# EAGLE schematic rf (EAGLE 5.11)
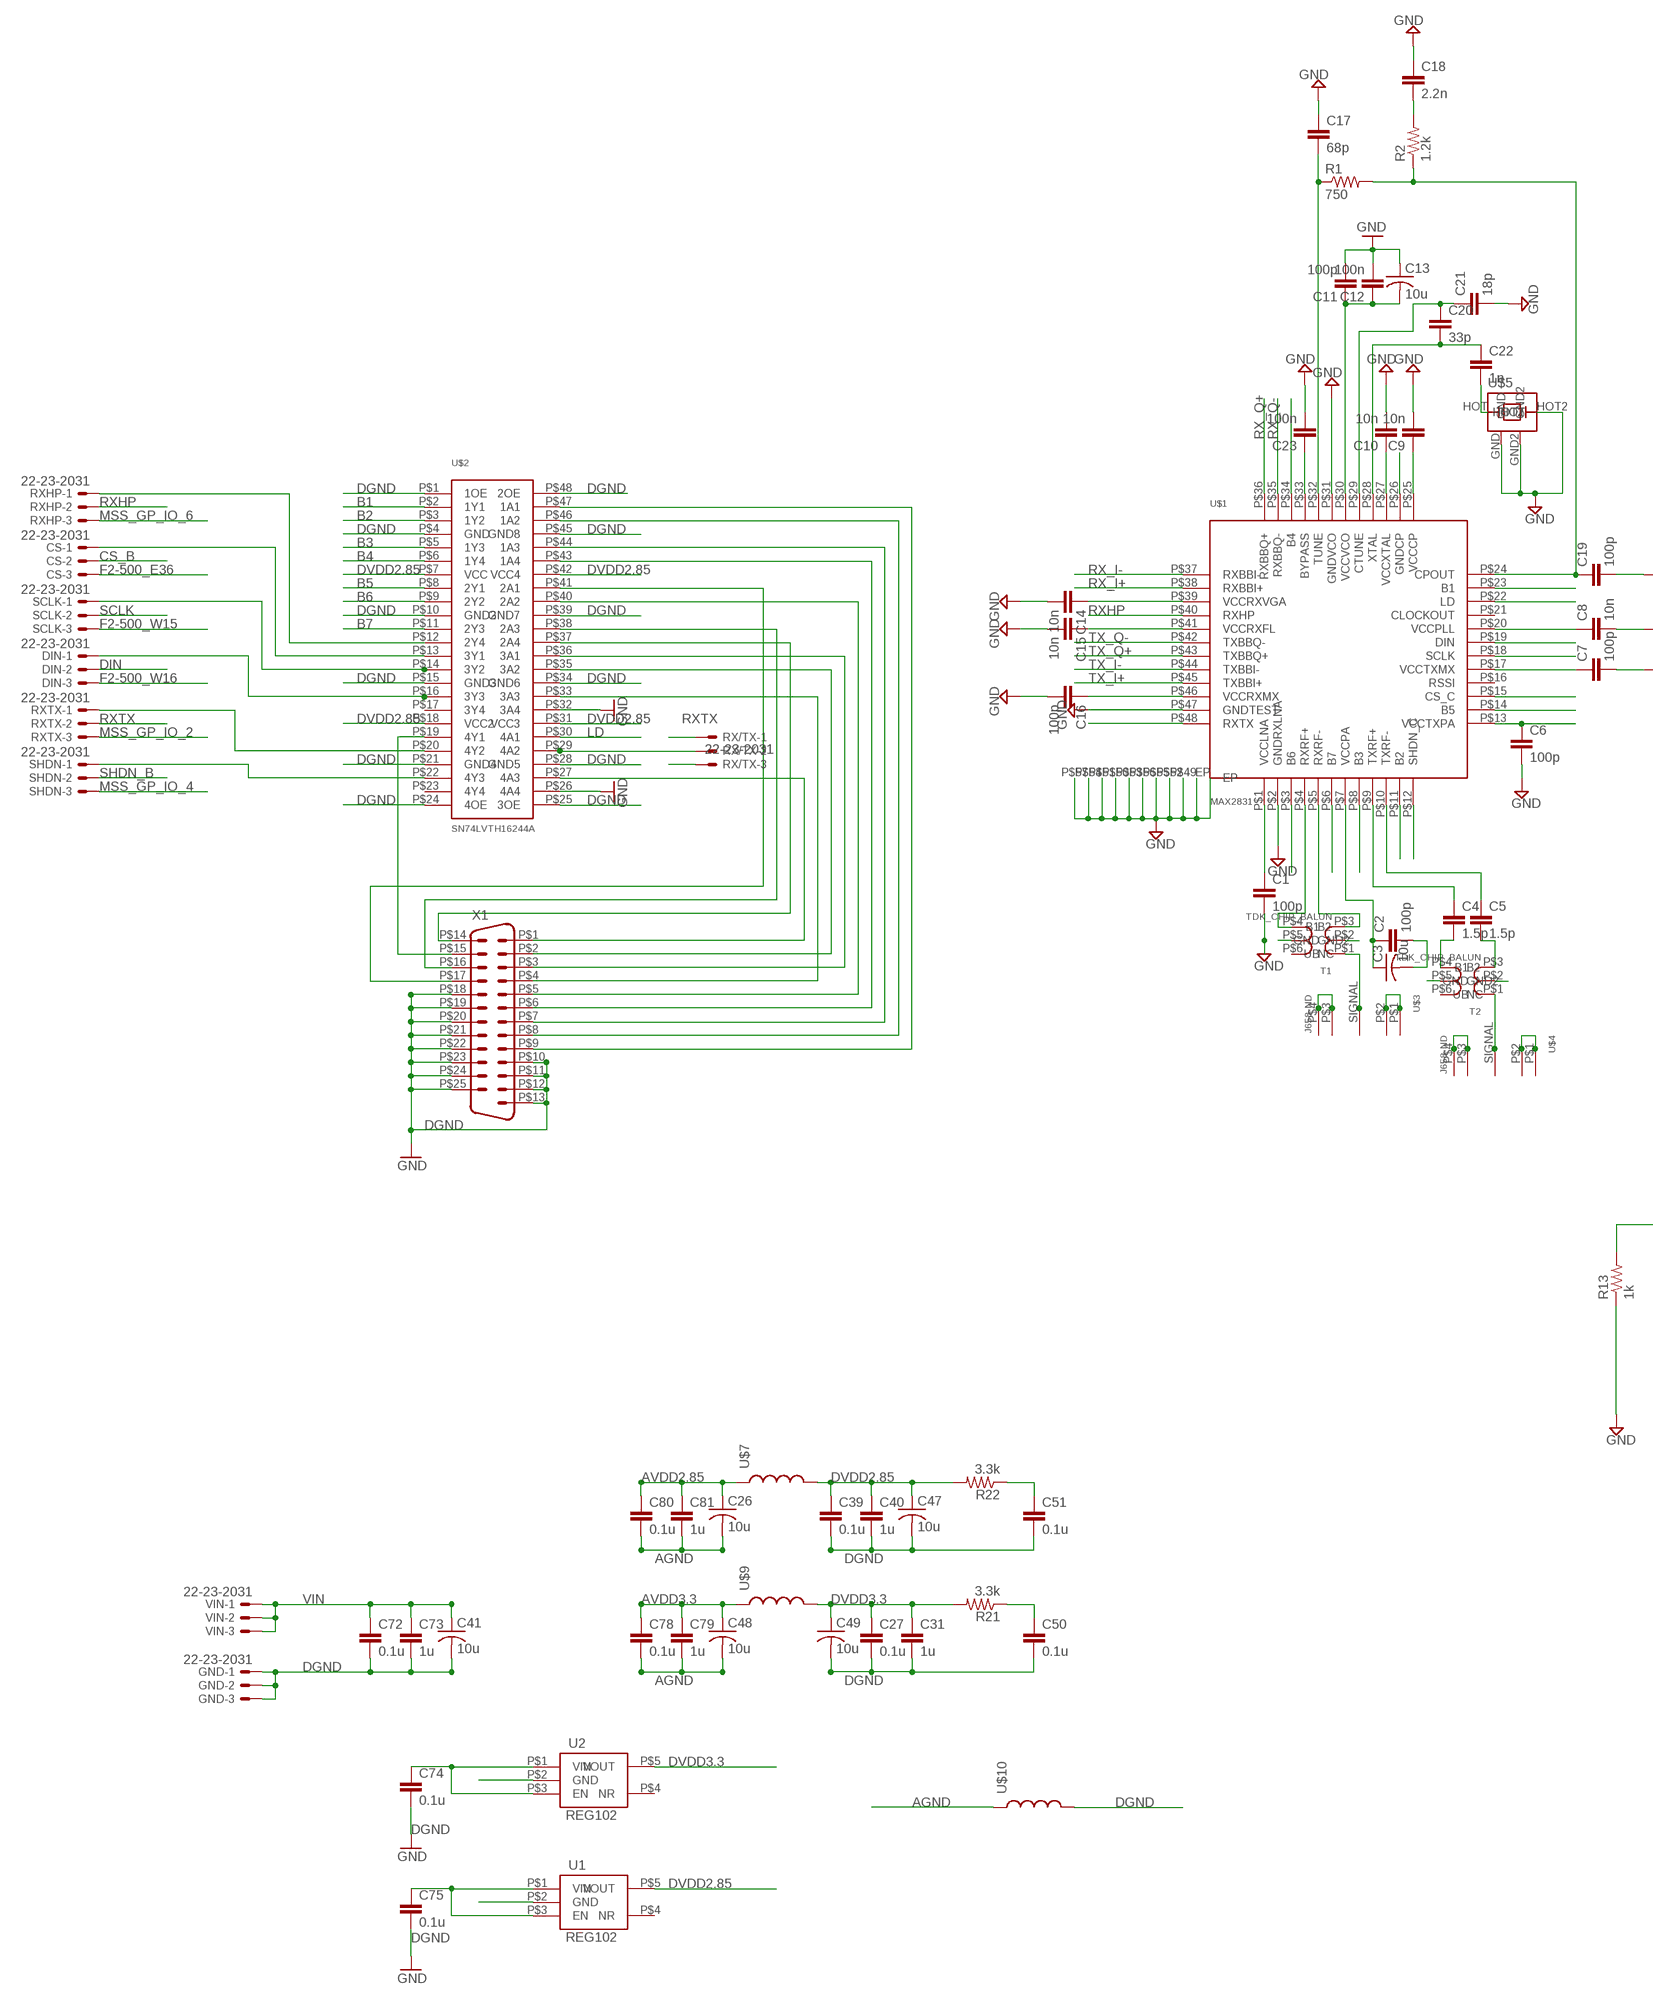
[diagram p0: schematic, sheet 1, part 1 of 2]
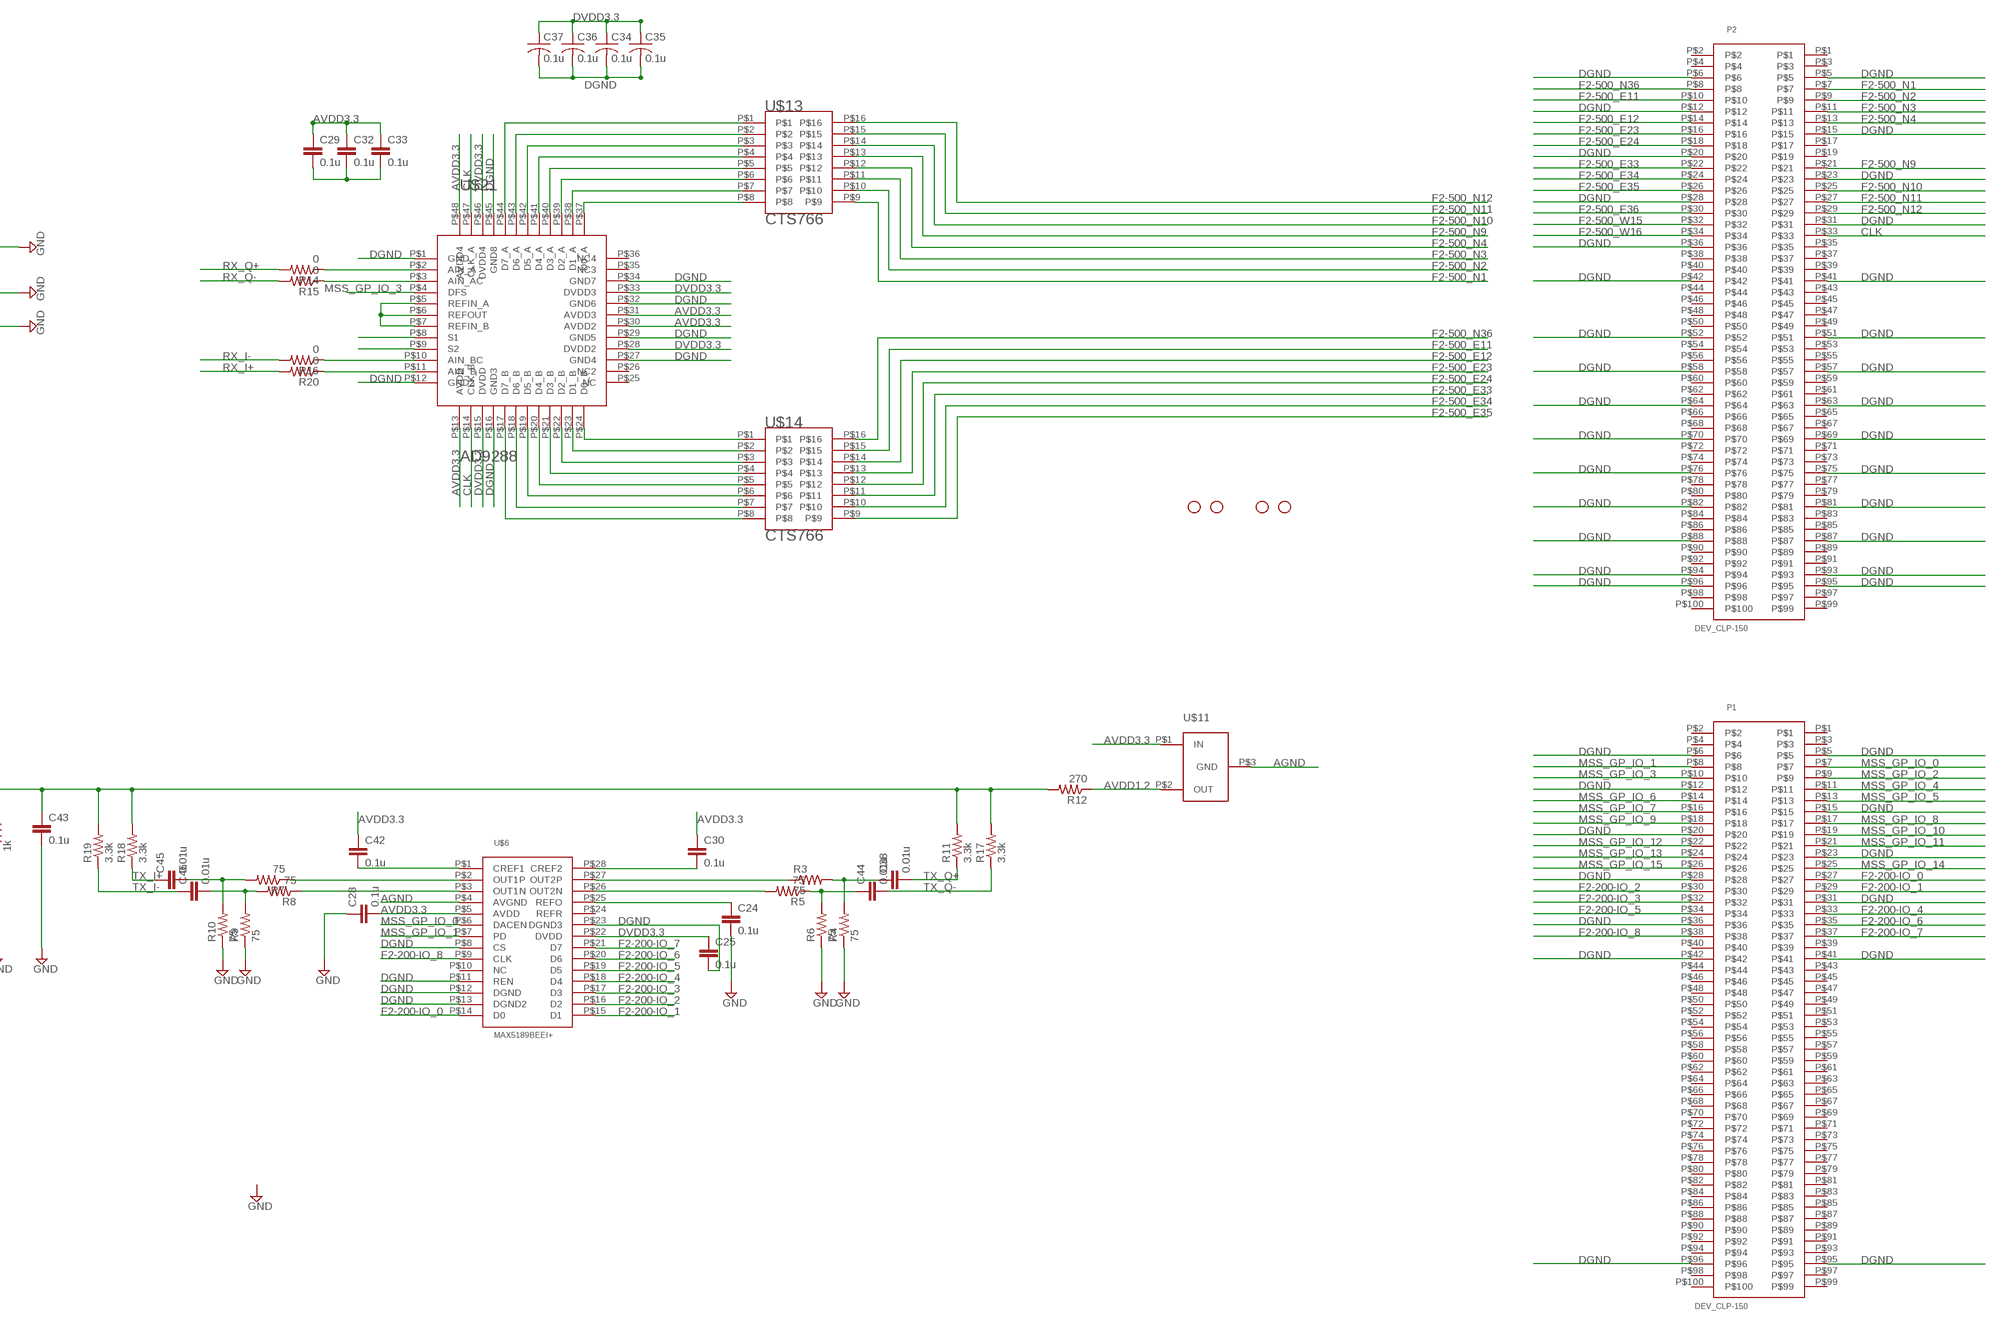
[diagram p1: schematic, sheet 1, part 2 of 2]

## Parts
C1  100p  CAP0402-CAP  [0402-CAP]
C2  100p  CAP0402-CAP  [0402-CAP]
C3  10u  C-USC0805  [C0805]
C4  1.5p  CAP0402-CAP  [0402-CAP]
C5  1.5p  CAP0402-CAP  [0402-CAP]
C6  100p  CAP0402-CAP  [0402-CAP]
C7  100p  CAP0402-CAP  [0402-CAP]
C8  10n  CAP0402-CAP  [0402-CAP]
C9  10n  CAP0402-CAP  [0402-CAP]
C10  10n  CAP0402-CAP  [0402-CAP]
C11  100p  CAP0402-CAP  [0402-CAP]
C12  100n  CAP0402-CAP  [0402-CAP]
C13  10u  C-USC0805  [C0805]
C14  10n  CAP0402-CAP  [0402-CAP]
C15  10n  CAP0402-CAP  [0402-CAP]
C16  100p  CAP0402-CAP  [0402-CAP]
C17  68p  CAP0402-CAP  [0402-CAP]
C18  2.2n  CAP0402-CAP  [0402-CAP]
C19  100p  CAP0402-CAP  [0402-CAP]
C20  33p  CAP0402-CAP  [0402-CAP]
C21  18p  CAP0402-CAP  [0402-CAP]
C22  1n  CAP0402-CAP  [0402-CAP]
C23  100n  CAP0402-CAP  [0402-CAP]
C24  0.1u  CAP0603-CAP  [0603-CAP]
C25  0.1u  CAP0603-CAP  [0603-CAP]
C26  10u  C-USC0805  [C0805]
C27  0.1u  CAP0603-CAP  [0603-CAP]
C28  0.1u  CAP0603-CAP  [0603-CAP]
C29  0.1u  CAP0603-CAP  [0603-CAP]
C30  0.1u  CAP0603-CAP  [0603-CAP]
C31  1u  CAP0603-CAP  [0603-CAP]
C32  0.1u  CAP0603-CAP  [0603-CAP]
C33  0.1u  CAP0603-CAP  [0603-CAP]
C34  0.1u  C-USC0603  [C0603]
C35  0.1u  C-USC0603  [C0603]
C36  0.1u  C-USC0603  [C0603]
C37  0.1u  C-USC0603  [C0603]
C38  0.01u  CAP0603-CAP  [0603-CAP]
C39  0.1u  CAP0603-CAP  [0603-CAP]
C40  1u  CAP0603-CAP  [0603-CAP]
C41  10u  C-USC0805  [C0805]
C42  0.1u  CAP0603-CAP  [0603-CAP]
C43  0.1u  CAP0603-CAP  [0603-CAP]
C44  0.01u  CAP0603-CAP  [0603-CAP]
C45  0.01u  CAP0603-CAP  [0603-CAP]
C46  0.01u  CAP0603-CAP  [0603-CAP]
C47  10u  C-USC0805  [C0805]
C48  10u  C-USC0805  [C0805]
C49  10u  C-USC0805  [C0805]
C50  0.1u  CAP0603-CAP  [0603-CAP]
C51  0.1u  CAP0603-CAP  [0603-CAP]
C72  0.1u  CAP0603-CAP  [0603-CAP]
C73  1u  CAP0603-CAP  [0603-CAP]
C74  0.1u  CAP0603-CAP  [0603-CAP]
C75  0.1u  CAP0603-CAP  [0603-CAP]
C78  0.1u  CAP0603-CAP  [0603-CAP]
C79  1u  CAP0603-CAP  [0603-CAP]
C80  0.1u  CAP0603-CAP  [0603-CAP]
C81  1u  CAP0603-CAP  [0603-CAP]
CS  22-23-2031  [22-23-2031]
DIN  22-23-2031  [22-23-2031]
GND  22-23-2031  [22-23-2031]
JP4  STAND-OFF  [STAND-OFF]
JP5  STAND-OFF  [STAND-OFF]
JP6  STAND-OFF  [STAND-OFF]
JP7  STAND-OFF  [STAND-OFF]
P1  DEV_CLP-150  [CLP-150]
P2  DEV_CLP-150  [CLP-150]
R1  750  RESISTOR0402-RES  [0402-RES]
R2  1.2k  RESISTOR0402-RES  [0402-RES]
R3  75  RESISTOR0603-RES  [0603-RES]
R4  75  RESISTOR0603-RES  [0603-RES]
R5  75  RESISTOR0603-RES  [0603-RES]
R6  75  RESISTOR0603-RES  [0603-RES]
R7  75  RESISTOR0603-RES  [0603-RES]
R8  75  RESISTOR0603-RES  [0603-RES]
R9  75  RESISTOR0603-RES  [0603-RES]
R10  75  RESISTOR0603-RES  [0603-RES]
R11  3.3k  RESISTOR0603-RES  [0603-RES]
R12  270  RESISTOR0603-RES  [0603-RES]
R13  1k  RESISTOR0603-RES  [0603-RES]
R14  0  RESISTOR0603-RES  [0603-RES]
R15  0  RESISTOR0603-RES  [0603-RES]
R16  0  RESISTOR0603-RES  [0603-RES]
R17  3.3k  RESISTOR0603-RES  [0603-RES]
R18  3.3k  RESISTOR0603-RES  [0603-RES]
R19  3.3k  RESISTOR0603-RES  [0603-RES]
R20  0  RESISTOR0603-RES  [0603-RES]
R21  3.3k  RESISTOR0603-RES  [0603-RES]
R22  3.3k  RESISTOR0603-RES  [0603-RES]
RX/TX  22-23-2031  [22-23-2031]
RXHP  22-23-2031  [22-23-2031]
RXTX  22-23-2031  [22-23-2031]
SCLK  22-23-2031  [22-23-2031]
SHDN  22-23-2031  [22-23-2031]
T1  TDK_CHIP_BALUN  [BALUN]
T2  TDK_CHIP_BALUN  [BALUN]
U1  REG102  [SOT-5]
U2  REG102  [SOT-5]
U$1  MAX2831  [TQFN-48]
U$2  SN74LVTH16244A  [TSSOP-48]
U$3  J658-ND  [SMA-SMD]
U$4  J658-ND  [SMA-SMD]
U$5  CX3225SB  [CX3225SB]
U$6  MAX5189BEEI+  [QSOP]
U$7  INDUCTOR0603  [0603]
U$9  INDUCTOR0603  [0603]
U$10  INDUCTOR0603  [0603]
U$11  MAX6601  [SOT-3]
U$13  CTS766  [SOIC-16]
U$14  CTS766  [SOIC-16]
U$21  AD9288  [LQFP(ST-48)]
VIN  22-23-2031  [22-23-2031]
X1  DB25  [DB25]

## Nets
AGND: C1.2 C2.2 C3.2 C6.2 C7.2 C8.2 C9.2 C10.2 C11.2 C12.2 C13.1 C14.2 C15.2 C16.2 C17.1 C18.1 C19.2 C21.2 C23.2 C24.2 C26.2 C28.1 C43.2 C48.2 C78.2 C79.2 C80.2 C81.2 R4.1 R6.1 R9.1 R10.1 R13.1 T1.P$2(GND) T1.P$5(GND2) T2.P$2(GND) T2.P$5(GND2) U$1.EP U$1.P$2(GNDRXLNA) U$1.P$26(GNDCP) U$1.P$31(GNDVCO) U$1.P$47(GNDTEST) U$1.P$49(EP_GND1) U$1.P$50(EP_GND2) U$1.P$51(EP_GND3) U$1.P$52(EP_GND4) U$1.P$53(EP_GND5) U$1.P$54(EP_GND6) U$1.P$55(EP_GND7) U$1.P$56(EP_GND8) U$1.P$57(EP_GND9) U$3.P$1(GND1) U$3.P$2(GND2) U$3.P$3(GND3) U$3.P$4(GND4) U$4.P$1(GND1) U$4.P$2(GND2) U$4.P$3(GND3) U$4.P$4(GND4) U$5.GND U$5.GND2 U$5.HOT2 U$6.P$4(AVGND) U$10.1 U$11.P$3(GND) ; supply symbol labelled GND
AVDD1.2: R12.1 U$11.P$2(OUT)
AVDD2.85: C1.1 C7.1 C8.1 C9.1 C10.1 C11.1 C12.1 C13.2 C14.1 C15.1 C16.1 C26.1 C80.1 C81.1 U$1.P$1(VCCLNA) U$1.P$17(VCCTXMX) U$1.P$20(VCCPLL) U$1.P$25(VCCCP) U$1.P$27(VCCXTAL) U$1.P$30(VCCVCO) U$1.P$39(VCCRXVGA) U$1.P$41(VCCRXFL) U$1.P$46(VCCRXMX) U$7.1
AVDD3.3: C2.1 C3.1 C6.1 C28.2 C29.1 C30.1 C32.1 C33.1 C42.1 C48.1 C78.1 C79.1 U$1.P$7(VCCPA) U$1.P$13(VCCTXPA) U$6.P$5(AVDD) U$9.1 U$11.P$1(IN) U$21.P$13(AVDD) U$21.P$30(AVDD2) U$21.P$31(AVDD3) U$21.P$48(AVDD4)
B1: U$1.P$23(B1) U$2.P$2(1Y1)
B2: U$1.P$11(B2) U$2.P$3(1Y2)
B3: U$1.P$8(B3) U$2.P$5(1Y3)
B4: U$1.P$34(B4) U$2.P$6(1Y4)
B5: U$1.P$14(B5) U$2.P$8(2Y1)
B6: U$1.P$3(B6) U$2.P$9(2Y2)
B7: U$1.P$6(B7) U$2.P$11(2Y3)
CLK: P2.P$33 U$21.P$14(CLK_B) U$21.P$47(CLK_A)
CS_B: CS.2 U$1.P$15(CS_C)
DGND: C25.2 C27.2 C29.2 C31.2 C32.2 C33.2 C34.2 C35.2 C36.2 C37.2 C39.2 C40.2 C41.2 C47.2 C49.2 C50.2 C51.2 C72.2 C73.2 C74.2 C75.2 GND.1 GND.2 GND.3 P1.P$5 P1.P$6 P1.P$12 P1.P$15 P1.P$20 P1.P$23 P1.P$28 P1.P$31 P1.P$36 P1.P$41 P1.P$42 P1.P$95 P1.P$96 P2.P$5 P2.P$6 P2.P$12 P2.P$15 P2.P$20 P2.P$23 P2.P$28 P2.P$31 P2.P$36 P2.P$41 P2.P$42 P2.P$51 P2.P$52 P2.P$57 P2.P$58 P2.P$63 P2.P$64 P2.P$69 P2.P$70 P2.P$75 P2.P$76 P2.P$81 P2.P$82 P2.P$87 P2.P$88 P2.P$93 P2.P$94 P2.P$95 P2.P$96 RX/TX.1 U1.P$2(GND) U2.P$2(GND) U$2.P$1(1OE) U$2.P$4(GND) U$2.P$10(GND2) U$2.P$15(GND3) U$2.P$21(GND4) U$2.P$24(4OE) U$2.P$25(3OE) U$2.P$26(4A4) U$2.P$28(GND5) U$2.P$32(3A4) U$2.P$34(GND6) U$2.P$39(GND7) U$2.P$45(GND8) U$2.P$48(2OE) U$6.P$8(CS) U$6.P$11(REN) U$6.P$12(DGND) U$6.P$13(DGND2) U$6.P$23(DGND3) U$10.2 U$21.P$1(GND) U$21.P$9(S2) U$21.P$12(GND2) U$21.P$16(GND3) U$21.P$27(GND4) U$21.P$29(GND5) U$21.P$32(GND6) U$21.P$34(GND7) U$21.P$45(GND8) X1.P$10 X1.P$11 X1.P$12 X1.P$13 X1.P$18 X1.P$19 X1.P$20 X1.P$21 X1.P$22 X1.P$23 X1.P$24 X1.P$25 ; supply symbol labelled GND
DIN: DIN.2 U$1.P$19(DIN)
DVDD2.85: C39.1 C40.1 C47.1 R22.2 RX/TX.3 U1.P$5(VOUT) U$2.P$7(VCC) U$2.P$18(VCC2) U$2.P$31(VCC3) U$2.P$42(VCC4) U$7.2
DVDD3.3: C25.1 C27.1 C31.1 C34.1 C35.1 C36.1 C37.1 C49.1 R21.2 U2.P$5(VOUT) U$6.P$22(DVDD) U$9.2 U$21.P$8(S1) U$21.P$15(DVDD) U$21.P$28(DVDD2) U$21.P$33(DVDD3) U$21.P$46(DVDD4)
F2-200-IO_0: P1.P$27 U$6.P$14(D0)
F2-200-IO_1: P1.P$29 U$6.P$15(D1)
F2-200-IO_2: P1.P$30 U$6.P$16(D2)
F2-200-IO_3: P1.P$32 U$6.P$17(D3)
F2-200-IO_4: P1.P$33 U$6.P$18(D4)
F2-200-IO_5: P1.P$34 U$6.P$19(D5)
F2-200-IO_6: P1.P$35 U$6.P$20(D6)
F2-200-IO_7: P1.P$37 U$6.P$21(D7)
F2-200-IO_8: P1.P$38 U$6.P$9(CLK)
F2-500_E11: P2.P$10 U$14.P$15
F2-500_E12: P2.P$14 U$14.P$14
F2-500_E23: P2.P$16 U$14.P$13
F2-500_E24: P2.P$18 U$14.P$12
F2-500_E33: P2.P$22 U$14.P$11
F2-500_E34: P2.P$24 U$14.P$10
F2-500_E35: P2.P$26 U$14.P$9
F2-500_E36: CS.3 P2.P$30
F2-500_N1: P2.P$7 U$13.P$9
F2-500_N2: P2.P$9 U$13.P$10
F2-500_N3: P2.P$11 U$13.P$11
F2-500_N4: P2.P$13 U$13.P$12
F2-500_N9: P2.P$21 U$13.P$13
F2-500_N10: P2.P$25 U$13.P$14
F2-500_N11: P2.P$27 U$13.P$15
F2-500_N12: P2.P$29 U$13.P$16
F2-500_N36: P2.P$8 U$14.P$16
F2-500_W15: P2.P$32 SCLK.3
F2-500_W16: DIN.3 P2.P$34
LD: U$1.P$22(LD) U$2.P$30(4A1)
MSS_GP_IO_0: P1.P$7 U$6.P$6(DACEN)
MSS_GP_IO_1: P1.P$8 U$6.P$7(PD)
MSS_GP_IO_2: P1.P$9 RXTX.3
MSS_GP_IO_3: P1.P$10 U$21.P$4(DFS)
MSS_GP_IO_4: P1.P$11 SHDN.3
MSS_GP_IO_5: P1.P$13
MSS_GP_IO_6: P1.P$14 RXHP.3
MSS_GP_IO_7: P1.P$16
MSS_GP_IO_8: P1.P$17
MSS_GP_IO_9: P1.P$18
MSS_GP_IO_10: P1.P$19
MSS_GP_IO_11: P1.P$21
MSS_GP_IO_12: P1.P$22
MSS_GP_IO_13: P1.P$24
MSS_GP_IO_14: P1.P$25
MSS_GP_IO_15: P1.P$26
N$1: RXHP.1 U$2.P$12(2Y4)
N$2: C38.1 R3.2 R4.2
N$3: C44.1 R5.1 R6.2
N$4: C46.2 R8.2 R9.2
N$5: T1.P$4(B2) U$1.P$4(RXRF+)
N$6: T1.P$3(B1) U$1.P$5(RXRF-)
N$7: U$2.P$27(4A3) X1.P$1
N$8: C4.1 U$1.P$9(TXRF+)
N$9: T1.P$1(UB) U$3.SIGNAL
N$10: C5.1 U$1.P$10(TXRF-)
N$11: C4.2 T2.P$4(B2)
N$12: C5.2 T2.P$3(B1)
N$13: RX/TX.2 U$2.P$29(4A2)
N$14: C17.2 R1.1 U$1.P$32(TUNE)
N$15: T2.P$1(UB) U$4.SIGNAL
N$16: C19.1 R1.2 R2.1 U$1.P$24(CPOUT)
N$17: C18.2 R2.2
N$18: C20.2 C22.1 U$1.P$28(XTAL)
N$19: C20.1 C21.1 U$1.P$29(CTUNE)
N$20: C22.2 U$5.HOT
N$21: C23.1 U$1.P$33(BYPASS)
N$22: C42.2 U$6.P$1(CREF1)
N$23: U$2.P$38(2A3) X1.P$16
N$24: C24.1 U$6.P$25(REFO)
N$25: CS.1 U$2.P$13(3Y1)
N$26: SCLK.1 U$2.P$14(3Y2)
N$27: C30.2 U$6.P$28(CREF2)
N$28: DIN.1 U$2.P$16(3Y3)
N$29: SHDN.1 U$2.P$22(4Y3)
N$30: RXTX.1 U$2.P$20(4Y2)
N$31: C45.2 R7.2 R10.2
N$32: U$2.P$35(3A2) X1.P$2
N$33: U$2.P$36(3A1) X1.P$3
N$34: U$2.P$33(3A3) X1.P$4
N$35: U$2.P$40(2A2) X1.P$5
N$36: U$2.P$43(1A4) X1.P$6
N$37: U$2.P$44(1A3) X1.P$7
N$38: U$2.P$46(1A2) X1.P$8
N$39: U$2.P$47(1A1) X1.P$9
N$40: U$2.P$37(2A4) X1.P$14
N$41: U$2.P$19(4Y1) X1.P$15
N$42: U$21.P$5(REFIN_A) U$21.P$6(REFOUT) U$21.P$7(REFIN_B)
N$43: U$14.P$1 U$21.P$24(D0_B)
N$44: U$14.P$2 U$21.P$23(D1_B)
N$45: U$14.P$3 U$21.P$22(D2_B)
N$46: U$14.P$4 U$21.P$21(D3_B)
N$47: U$14.P$5 U$21.P$20(D4_B)
N$48: U$14.P$6 U$21.P$19(D5_B)
N$49: U$14.P$7 U$21.P$18(D6_B)
N$50: U$14.P$8 U$21.P$17(D7_B)
N$51: U$13.P$8 U$21.P$37(D0_A)
N$52: U$13.P$7 U$21.P$38(D1_A)
N$53: U$13.P$6 U$21.P$39(D2_A)
N$54: U$13.P$5 U$21.P$40(D3_A)
N$55: U$13.P$4 U$21.P$41(D4_A)
N$56: U$13.P$3 U$21.P$42(D5_A)
N$57: U$13.P$2 U$21.P$43(D6_A)
N$58: U$13.P$1 U$21.P$44(D7_A)
N$59: U$2.P$41(2A1) X1.P$17
N$60: R7.1 U$6.P$2(OUT1P)
N$61: R8.1 U$6.P$3(OUT1N)
N$62: R5.2 U$6.P$26(OUT2N)
N$63: R3.1 U$6.P$27(OUT2P)
N$64: C43.1 R11.2 R12.2 R13.2 R17.2 R18.2 R19.2
N$65: R14.1 U$21.P$2(AIN_A)
N$66: R15.1 U$21.P$3(AIN_AC)
N$67: R16.1 U$21.P$10(AIN_BC)
N$68: R20.1 U$21.P$11(AIN_B)
N$69: C51.1 R22.1
N$70: C50.1 R21.1
RX_I+: R20.2 U$1.P$38(RXBBI+)
RX_I-: R16.2 U$1.P$37(RXBBI-)
RX_Q+: R14.2 U$1.P$36(RXBBQ+)
RX_Q-: R15.2 U$1.P$35(RXBBQ-)
RXHP: RXHP.2 U$1.P$40(RXHP)
RXTX: RXTX.2 U$1.P$48(RXTX)
SCLK: SCLK.2 U$1.P$18(SCLK)
SHDN_B: SHDN.2 U$1.P$12(SHDN_C)
TX_I+: C45.1 R18.1 U$1.P$45(TXBBI+)
TX_I-: C46.1 R19.1 U$1.P$44(TXBBI-)
TX_Q+: C38.2 R11.1 U$1.P$43(TXBBQ+)
TX_Q-: C44.2 R17.1 U$1.P$42(TXBBQ-)
VIN: C41.1 C72.1 C73.1 C74.1 C75.1 U1.P$1(VIN) U1.P$3(EN) U2.P$1(VIN) U2.P$3(EN) VIN.1 VIN.2 VIN.3
Unconnected: P1.P$1 P1.P$2 P1.P$3 P1.P$4 P1.P$39 P1.P$40 P1.P$43 P1.P$44 P1.P$45 P1.P$46 P1.P$47 P1.P$48 P1.P$49 P1.P$50 P1.P$51 P1.P$52 P1.P$53 P1.P$54 P1.P$55 P1.P$56 P1.P$57 P1.P$58 P1.P$59 P1.P$60 P1.P$61 P1.P$62 P1.P$63 P1.P$64 P1.P$65 P1.P$66 P1.P$67 P1.P$68 P1.P$69 P1.P$70 P1.P$71 P1.P$72 P1.P$73 P1.P$74 P1.P$75 P1.P$76 P1.P$77 P1.P$78 P1.P$79 P1.P$80 P1.P$81 P1.P$82 P1.P$83 P1.P$84 P1.P$85 P1.P$86 P1.P$87 P1.P$88 P1.P$89 P1.P$90 P1.P$91 P1.P$92 P1.P$93 P1.P$94 P1.P$97 P1.P$98 P1.P$99 P1.P$100 P2.P$1 P2.P$2 P2.P$3 P2.P$4 P2.P$17 P2.P$19 P2.P$35 P2.P$37 P2.P$38 P2.P$39 P2.P$40 P2.P$43 P2.P$44 P2.P$45 P2.P$46 P2.P$47 P2.P$48 P2.P$49 P2.P$50 P2.P$53 P2.P$54 P2.P$55 P2.P$56 P2.P$59 P2.P$60 P2.P$61 P2.P$62 P2.P$65 P2.P$66 P2.P$67 P2.P$68 P2.P$71 P2.P$72 P2.P$73 P2.P$74 P2.P$77 P2.P$78 P2.P$79 P2.P$80 P2.P$83 P2.P$84 P2.P$85 P2.P$86 P2.P$89 P2.P$90 P2.P$91 P2.P$92 P2.P$97 P2.P$98 P2.P$99 P2.P$100 T1.P$6(NC) T2.P$6(NC) U1.P$4(NR) U2.P$4(NR) U$1.P$16(RSSI) U$1.P$21(CLOCKOUT) U$2.P$17(3Y4) U$2.P$23(4Y4) U$6.P$10(NC) U$6.P$24(REFR) U$21.P$25(NC) U$21.P$26(NC2) U$21.P$35(NC3) U$21.P$36(NC4)

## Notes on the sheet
- RXTX

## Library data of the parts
C1 C2 C4-C12 C14-C25 C27-C33 C38-C40 C42-C46 C50 C51 C72-C75 C78-C81 = SparkFun:CAP: Capacitor
C3 C13 C26 C34-C37 C41 C47-C49 = rcl:C-US: CAPACITOR, American symbol
CS DIN GND RX/TX RXHP RXTX SCLK SHDN VIN = con-molex:22-23-2031: .100" (2.54mm) Center Header - 3 Pin; MF: MOLEX; MPN: 22-23-2031; OC_FARNELL: 1462950; OC_NEWARK: 30C0862
JP4-JP7 = SparkFun:STAND-OFF: Stand Off
P1 P2 = EECS370:DEV_CLP-150
R1-R22 = SparkFun:RESISTOR: Resistor
T1 T2 = sam:TDK_CHIP_BALUN
U1 U2 = sam:REG102
U$1 = sam:MAX2831
U$2 = sam:SN74LVTH16244A
U$3 U$4 = sam:J658-ND
U$5 = sam:CX3225SB
U$6 = sam:MAX5189BEEI+
U$7 U$9 U$10 = SparkFun:INDUCTOR: Inductors
U$11 = sam:MAX6601
U$13 U$14 = sam:CTS766
U$21 = sam:AD9288
X1 = sam:DB25: SUB-D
